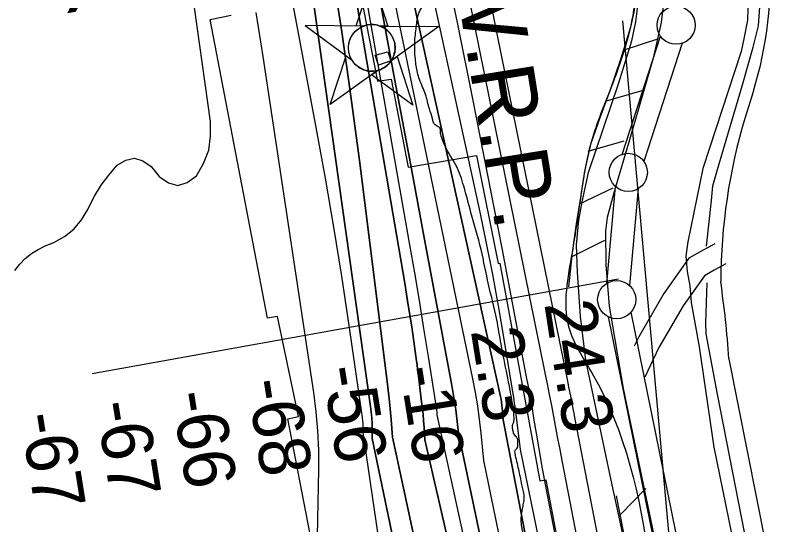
# Model space of a CAD drawing. Extents: x 3392644 to 3430565, y 576657 to 602123.
# Drawn here: x 3414227 to 3415220, y 582620 to 583288 of the extents above; entities that cross this region are included whole.
import ezdxf

# ---------------------------------------------------------------- set-up
doc = ezdxf.new("R2010")
doc.units = 0
for name, color, linetype in [('V-CHAN-DOCK', 7, 'Continuous'), ('V-CHAN-NAID', 7, 'Continuous'), ('V-FLOD-BASE', 7, 'Continuous'), ('V-LEVE-TOET', 7, 'Continuous'), ('V-RIVR-EDGE', 7, 'Continuous'), ('V-RIVR-RANG', 7, 'Continuous'), ('V-ROAD-CNTR', 7, 'Continuous'), ('V-RRAP-FSHR', 7, 'Continuous'), ('V-RRAP-RVMT', 7, 'Continuous'), ('V-SURV-LINE', 7, 'Continuous'), ('V-TOPO-DPTH', 7, 'Continuous'), ('V-TOPO-MAJR', 7, 'Continuous'), ('V-TOPO-MINR', 7, 'Continuous'), ('V-TOPO-SHOR', 7, 'Continuous'), ('V-TOPO-WATR', 7, 'Continuous'), ('V-TOPO-WATR-IDEN', 7, 'Continuous')]:
    doc.layers.add(name, color=color, linetype=linetype)

msp = doc.modelspace()

# ---------------------------------------------------------------- linework, layer by layer
at = {"layer": 'V-CHAN-DOCK'}
msp.add_lwpolyline([(3414698.49, 583235.12), (3414714.97, 583239.56), (3414719.19, 583227.57), (3414703, 583222.05), (3414698.49, 583235.12)], dxfattribs=at)
at = {"layer": 'V-CHAN-NAID'}
for points in [[(3414683.27, 583273.27), (3414673.69, 583273.34), (3414694.81, 583336.82), (3414715.04, 583273.04), (3414705.45, 583273.11), (3414703.87, 583273.69), (3414701.78, 583274.31), (3414699.74, 583274.76), (3414697.7, 583275.07), (3414696.54, 583275.18), (3414695, 583275.26), (3414693.28, 583275.26), (3414691.91, 583275.19), (3414690, 583274.99), (3414688.64, 583274.77), (3414686.85, 583274.39), (3414685.32, 583273.97), (3414684.29, 583273.64)], [(3414683.27, 583273.27), (3414606.78, 583273.81), (3414668.35, 583228.41), (3414667.24, 583230.32), (3414666.43, 583231.95), (3414665.6, 583233.92), (3414664.91, 583235.97), (3414664.54, 583237.29), (3414664.18, 583238.92), (3414663.94, 583240.37), (3414663.75, 583241.96), (3414663.64, 583243.7), (3414663.63, 583245.28), (3414663.73, 583247.35), (3414663.92, 583248.97), (3414664.31, 583251.18), (3414664.79, 583253.1), (3414665.39, 583254.99), (3414666.05, 583256.66), (3414666.77, 583258.25), (3414667.59, 583259.79), (3414668.65, 583261.52), (3414669.68, 583262.99), (3414670.68, 583264.26), (3414671.68, 583265.41), (3414672.99, 583266.75), (3414674.04, 583267.71), (3414675.76, 583269.11), (3414676.97, 583269.98), (3414678.66, 583271.05), (3414680.39, 583271.99), (3414681.83, 583272.68)], [(3414705.45, 583273.11), (3414781.94, 583272.57), (3414719.74, 583228.05), (3414720.65, 583229.54), (3414721.63, 583231.38), (3414722.34, 583232.97), (3414723.08, 583234.92), (3414723.63, 583236.71), (3414724.03, 583238.35), (3414724.39, 583240.36), (3414724.57, 583241.93), (3414724.7, 583244.14), (3414724.67, 583246.2), (3414724.48, 583248.42), (3414724.21, 583250.18), (3414723.72, 583252.41), (3414723.08, 583254.55), (3414722.33, 583256.53), (3414721.68, 583257.97), (3414720.68, 583259.89), (3414719.62, 583261.61), (3414718.4, 583263.31), (3414717.14, 583264.85), (3414715.87, 583266.22), (3414714.24, 583267.75), (3414712.49, 583269.16), (3414710.81, 583270.34), (3414708.92, 583271.47), (3414707.45, 583272.23)], [(3414701.71, 583215.14), (3414639.51, 583170.62), (3414660.63, 583234.1), (3414668.35, 583228.41), (3414668.98, 583227.45), (3414670.37, 583225.59), (3414671.58, 583224.17), (3414673.05, 583222.67), (3414674.44, 583221.42), (3414675.89, 583220.26), (3414677.29, 583219.28), (3414678.97, 583218.24), (3414680.68, 583217.33), (3414682.48, 583216.52), (3414683.92, 583215.96), (3414685.55, 583215.43), (3414687.77, 583214.87), (3414689.31, 583214.58), (3414691.33, 583214.33), (3414692.87, 583214.22), (3414694.73, 583214.2), (3414696.42, 583214.28), (3414698.13, 583214.45), (3414700.03, 583214.76)], [(3414719.74, 583228.05), (3414727.54, 583233.63), (3414747.76, 583169.85), (3414693.91, 583209.56), (3414701.71, 583215.14), (3414703.38, 583215.62), (3414704.99, 583216.18), (3414707.15, 583217.09), (3414708.88, 583217.98), (3414710.75, 583219.09), (3414712.48, 583220.3), (3414714.04, 583221.55), (3414715.32, 583222.71), (3414716.71, 583224.13), (3414717.91, 583225.54), (3414719.03, 583227.01)]]:
    msp.add_lwpolyline(points, close=True, dxfattribs=at)
msp.add_circle((3414694.16, 583244.74), 30.54, dxfattribs=at)
at = {"layer": 'V-FLOD-BASE'}
msp.add_lwpolyline([(3415036.15, 583594.1), (3415059.92, 583478.61), (3415075.05, 583377.75), (3415077.8, 583343.95), (3415077.17, 583313.67), (3415072.99, 583277.94), (3415062.38, 583231.33), (3415031.25, 583124.55), (3415011.97, 583058.15), (3415002.28, 583022.54), (3414999.86, 583005.37), (3415000.31, 582960.6), (3415004.71, 582906.8), (3415023.14, 582798.99), (3415063.23, 582606.71), (3415128.06, 582278.27), (3415163.25, 582111.18)], dxfattribs=at)
at = {"layer": 'V-LEVE-TOET'}
for points in [[(3415186.6, 583312.7), (3415185.94, 583281.04), (3415181.3, 583256.35), (3415177.52, 583239.9), (3415127.52, 583086.67), (3415107.63, 582990.68), (3415105.18, 582972.13), (3415106.83, 582952.13), (3415110.57, 582933.46), (3415112.19, 582911.39), (3415122.69, 582853.32), (3415142.01, 582722.08), (3415168.89, 582589.99), (3415225.17, 582314.75), (3415263.58, 582111.54)], [(3415131.02, 582111.06), (3415130.78, 582112.21), (3415086.3, 582325.92), (3415049.01, 582487.15), (3415007.52, 582678.76), (3414974.27, 582835.77), (3414967.2, 582893.07), (3414963.57, 582950.99), (3414962.25, 582986.83), (3414964.98, 583019.14), (3414969.61, 583043.15), (3414977.98, 583081.54), (3415016.89, 583197.8), (3415034.57, 583253.91), (3415039.91, 583278.59), (3415043.24, 583306.75)]]:
    msp.add_lwpolyline(points, dxfattribs=at)
at = {"layer": 'V-RIVR-EDGE'}
msp.add_spline([(3415011.94, 582110.63), (3415011.25, 582113.67), (3415005.32, 582138.35), (3414994.86, 582182.43), (3414988.58, 582209.22), (3414983.35, 582231.44), (3414985.12, 582233.19), (3414986.19, 582238.83), (3414984.79, 582244.82), (3414980.24, 582254.7), (3414972.18, 582274.8), (3414966.59, 582294.55), (3414960.3, 582316.41), (3414955.45, 582346.73), (3414949.18, 582375.99), (3414950.95, 582383.04), (3414951.67, 582387.62), (3414950.97, 582391.14), (3414945.72, 582402.78), (3414945.03, 582408.42), (3414945.04, 582414.41), (3414949.28, 582417.22), (3414948.23, 582420.4), (3414946.12, 582423.22), (3414938.73, 582427.47), (3414936.98, 582430.64), (3414936.99, 582436.28), (3414937.02, 582447.2), (3414934.93, 582458.84), (3414931.08, 582468.71), (3414926.53, 582481.41), (3414920.24, 582500.45), (3414911.86, 582534.3), (3414906.27, 582553.7), (3414906.29, 582561.1), (3414906.31, 582567.09), (3414904.56, 582573.79), (3414896.86, 582596.71), (3414892.32, 582609.76), (3414889.88, 582622.45), (3414889.9, 582631.96), (3414892.05, 582644.64), (3414893.48, 582651.69), (3414893.49, 582658.74), (3414890.71, 582672.84), (3414886.53, 582692.93), (3414881.65, 582714.09), (3414881.66, 582717.61), (3414884.84, 582721.48), (3414885.2, 582726.06), (3414885.22, 582732.05), (3414882.41, 582736.64), (3414880.3, 582739.11), (3414878.91, 582744.4), (3414878.21, 582748.98), (3414879.99, 582755.32), (3414880.36, 582760.61), (3414876.9, 582787.39), (3414871.33, 582816.66), (3414863.33, 582856.85), (3414857.77, 582888.93), (3414846.96, 582935.11), (3414837.21, 582980.59), (3414823.94, 583029.25), (3414814.51, 583063.81), (3414804.71, 583090.26), (3414795.23, 583106.5), (3414789.62, 583117.08), (3414785.77, 583126.96), (3414784.03, 583135.42), (3414784.04, 583138.94), (3414782.28, 583140.71), (3414777, 583143.89), (3414774.54, 583148.13), (3414773.5, 583152.36), (3414769.65, 583164.7), (3414764.41, 583183.74), (3414756.71, 583203.14), (3414753.91, 583212.31), (3414751.14, 583230.29), (3414750.49, 583254.25), (3414752.66, 583274.68), (3414756.22, 583291.24), (3414759.05, 583296.52), (3414762.6, 583304.61), (3414762.97, 583313.77), (3414763, 583322.93), (3414759.15, 583333.51), (3414751.07, 583343.75), (3414748.26, 583350.1), (3414748.27, 583353.27), (3414745.82, 583358.57), (3414741.95, 583363.86), (3414741.61, 583366.33), (3414743.04, 583373.73), (3414742.35, 583381.83), (3414734.29, 583399.47), (3414725.87, 583414.29), (3414718.49, 583423.12), (3414711.1, 583426.66), (3414699.48, 583428.1), (3414691.38, 583433.4), (3414685.06, 583440.12), (3414679.79, 583448.94), (3414677.37, 583465.15), (3414677.39, 583475.02), (3414685.18, 583487.33), (3414688.37, 583497.9), (3414689.82, 583515.16), (3414691.27, 583528.19), (3414691.65, 583541.94), (3414694.16, 583557.08), (3414696.67, 583573.99), (3414700.9, 583576.8), (3414705.48, 583576.79), (3414712.53, 583576.77), (3414714.65, 583578.17), (3414715.71, 583581.69), (3414716.08, 583589.09), (3414715.07, 583606.71), (3414713.7, 583624.69), (3414709.53, 583645.14), (3414702.19, 583671.58), (3414689.95, 583708.26), (3414675.26, 583753.4), (3414668.97, 583773.15), (3414667.95, 583789.71), (3414665.86, 583797.47), (3414663.78, 583814.39), (3414662.06, 583831.31), (3414657.55, 583856.69), (3414652.01, 583896.52), (3414646.08, 583921.2), (3414638.07, 583960.69), (3414633.91, 583989.95), (3414631.51, 584016.73), (3414630.52, 584040.7), (3414627.38, 584055.51), (3414624.59, 584068.2), (3414615.13, 584089.36), (3414609.17, 584100.65), (3414604.63, 584118.64), (3414602.91, 584134.15), (3414602.94, 584148.24), (3414607.92, 584164.09), (3414607.59, 584174.66), (3414606.56, 584186.29), (3414603.08, 584202.15), (3414597.84, 584221.9), (3414587.01, 584259.28), (3414577.21, 584284.67), (3414563.19, 584316.07), (3414556.89, 584333.7), (3414552.7, 584347.81), (3414552.72, 584358.38), (3414554.86, 584366.48), (3414565.48, 584386.54), (3414574.33, 584406.25), (3414577.89, 584417.16), (3414577.2, 584425.27), (3414574.75, 584433.03), (3414570.55, 584441.85), (3414564.57, 584448.21), (3414550.49, 584454.23), (3414538.53, 584460.25), (3414527.27, 584467.33), (3414521.29, 584472.28), (3414516.02, 584479.69)], degree=3, dxfattribs=at)
at = {"layer": 'V-RIVR-RANG'}
msp.add_line((3415017.16, 582942.05), (3414328.24, 582817.95), dxfattribs=at)
at = {"layer": 'V-ROAD-CNTR'}
for points in [[(3415193.63, 583188.38), (3415182.82, 583153.67)], [(3415143.34, 582988.29), (3415127.79, 582979.8), (3415109.26, 582969.28), (3415076.52, 582923.4), (3415043.51, 582866.67), (3415037.66, 582854.44)], [(3415157.72, 582961.97), (3415142.39, 582953.59), (3415129.83, 582946.46), (3415101.75, 582907.11), (3415070.05, 582852.64), (3415051.38, 582813.55)], [(3415161.6, 582837.88), (3415305.19, 582114.83)]]:
    msp.add_lwpolyline(points, dxfattribs=at)
for centre, radius, start, end in [((3414715.18, 583336.43), 500.83, 342.80694, 3.91232), ((3415912.22, 582935.16), 761.43, 163.32294, 179.71114), ((3413810.02, 582744.59), 1354.8, 3.94851, 8.25016)]:
    msp.add_arc(centre, radius, start, end, dxfattribs=at)
at = {"layer": 'V-RRAP-FSHR'}
for p, q in [((3415023.35, 583241.78), (3415069.82, 583256.78)), ((3415001.29, 583175.35), (3415048.14, 583189.1)), ((3414977.41, 583109.56), (3415024.33, 583123.08)), ((3414965.92, 583040.42), (3415009.9, 583061.63)), ((3414955.47, 582971.21), (3414999.14, 582993.07)), ((3415018.85, 582632.86), (3415052.7, 582668.06))]:
    msp.add_line(p, q, dxfattribs=at)
for points in [[(3415003.54, 583533.19), (3415007.38, 583520.3), (3415020.28, 583473.21), (3415031.99, 583425.41), (3415038.57, 583387.28), (3415041.24, 583349.1), (3415039.96, 583310.51), (3415037.18, 583291.23), (3415032.65, 583271.99), (3415019.61, 583229.65), (3415005.65, 583188.27), (3414992.43, 583153.35), (3414980.31, 583118.03), (3414973.2, 583085.1), (3414967.78, 583051.84), (3414961.85, 583014.41), (3414956.32, 582976.94), (3414951.47, 582932.04)], [(3415013.81, 582658.47), (3415032.62, 582562.77), (3415083.41, 582306.35), (3415123.42, 582111.03)]]:
    msp.add_lwpolyline(points, dxfattribs=at)
msp.add_spline([(3414988.21, 583582.96), (3415007.38, 583520.3), (3415031.99, 583425.41), (3415041.24, 583349.1), (3415032.65, 583271.99), (3415005.65, 583188.27), (3414980.31, 583118.03), (3414967.78, 583051.84), (3414956.32, 582976.94), (3414951.65, 582879.9), (3414982.23, 582819.21), (3415083.41, 582306.35), (3415123.24, 582111.03)], degree=3, dxfattribs=at)
at = {"layer": 'V-RRAP-RVMT'}
for p, q in [((3414662.43, 583403.08), (3414701.64, 583200.99)), ((3414482.37, 583281.92), (3414509.93, 583287.51)), ((3414557.7, 582890.74), (3414482.37, 583281.92)), ((3414701.64, 583200.99), (3414719.54, 583203.91)), ((3414719.54, 583203.91), (3414741.67, 583088.44)), ((3414741.67, 583088.44), (3414831.08, 583103.97)), ((3414831.08, 583103.97), (3414859.57, 582962.59)), ((3414859.57, 582962.59), (3414861.92, 582962.91)), ((3414861.92, 582962.91), (3414914.23, 582678.2)), ((3414570.67, 582893.01), (3414557.7, 582890.74)), ((3414598.01, 582762.25), (3414570.67, 582893.01)), ((3414584.21, 582759.11), (3414598.01, 582762.25)), ((3414637.55, 582483.52), (3414584.21, 582759.11)), ((3414914.23, 582678.2), (3414921.73, 582679.37)), ((3414921.73, 582679.37), (3414949.69, 582533.57))]:
    msp.add_line(p, q, dxfattribs=at)
at = {"layer": 'V-SURV-LINE'}
for points in [[(3415021.77, 583105.33), (3415072.05, 583260.01)], [(3415100.59, 583250.75), (3415050.31, 583096.07)], [(3415001.59, 582936.41), (3415013.12, 583063.16)], [(3415042.99, 583060.44), (3415031.47, 582933.7)], [(3415033.4, 582898.58), (3415193.35, 582111.29)], [(3415162.76, 582111.17), (3415004.01, 582892.59)]]:
    msp.add_lwpolyline(points, dxfattribs=at)
for centre in [(3415092.5, 583274.39), (3415029.86, 583081.69), (3415014.72, 582915.16)]:
    msp.add_circle(centre, 25, dxfattribs=at)
at = {"layer": 'V-TOPO-DPTH'}
for points in [[(3414406.42, 584941.91), (3414522.36, 584270.42), (3414522.43, 584270.03), (3414522.49, 584269.65), (3414522.89, 584267.36), (3414523.1, 584266.25), (3414523.28, 584265.32), (3414635.45, 583677.6), (3414642.03, 583643), (3414648.57, 583608.4), (3414655.07, 583573.79), (3414661.54, 583539.17), (3414686.49, 583405.14), (3414705.42, 583303.5), (3414724.35, 583201.87), (3414743.31, 583100.24), (3414762.28, 582998.61), (3414798.86, 582802.66), (3414801.56, 582787.11), (3414803.98, 582771.52), (3414806, 582755.88), (3414807.76, 582740.19), (3414939.76, 582110.36)], [(3414406.42, 584941.91), (3414522.36, 584270.42), (3414522.43, 584270.03), (3414522.49, 584269.65), (3414522.89, 584267.36), (3414523.1, 584266.25), (3414523.28, 584265.32), (3414635.45, 583677.6), (3414642.03, 583643), (3414648.57, 583608.4), (3414655.07, 583573.79), (3414661.54, 583539.17), (3414686.49, 583405.14), (3414705.42, 583303.5), (3414724.35, 583201.87), (3414743.31, 583100.24), (3414762.28, 582998.61), (3414798.86, 582802.66), (3414801.56, 582787.11), (3414803.98, 582771.52), (3414806, 582755.88), (3414807.76, 582740.19), (3414939.76, 582110.36)], [(3414906.69, 582110.24), (3414763.53, 582731.67), (3414763.06, 582739.96), (3414762.54, 582748.25), (3414761.91, 582756.53), (3414761.18, 582764.81), (3414760.31, 582773.07), (3414759.35, 582781.32), (3414754.22, 582822.25), (3414750.43, 582850.93), (3414746.39, 582879.57), (3414741.95, 582908.15), (3414737.26, 582936.7), (3414630.27, 583560.78)], [(3414630.27, 583560.78), (3414737.26, 582936.7), (3414741.95, 582908.15), (3414746.39, 582879.57), (3414750.43, 582850.93), (3414754.22, 582822.25), (3414759.35, 582781.32), (3414760.31, 582773.07), (3414761.18, 582764.81), (3414761.91, 582756.53), (3414762.54, 582748.25), (3414763.06, 582739.96), (3414763.53, 582731.67), (3414906.69, 582110.24)], [(3414824.64, 582109.94), (3414694.58, 582733.54), (3414694.69, 582743.99), (3414694.43, 582754.42), (3414693.61, 582764.82), (3414692.43, 582775.2), (3414596.3, 583456.6)], [(3414824.64, 582109.94), (3414694.58, 582733.54), (3414694.69, 582743.99), (3414694.43, 582754.42), (3414693.61, 582764.82), (3414692.43, 582775.2), (3414596.3, 583456.6)], [(3415030.39, 582110.69), (3414926.34, 582648.14), (3414921.96, 582671.21), (3414917.71, 582694.3), (3414913.62, 582717.42), (3414909.66, 582740.57), (3414906.86, 582757.28), (3414904.33, 582772.08), (3414901.74, 582786.86), (3414899.05, 582801.62), (3414896.29, 582816.37), (3414864.68, 582982.61), (3414845.77, 583080.42), (3414826.46, 583178.14), (3414806.55, 583275.74), (3414786.23, 583373.26)], [(3414856.12, 582110.06), (3414721.22, 582735.12), (3414719.67, 582758.36), (3414717.49, 582781.55), (3414714.89, 582804.7), (3414677.97, 583097.2), (3414666.76, 583181.41), (3414654.81, 583265.51), (3414641.72, 583349.44)], [(3414641.72, 583349.44), (3414654.81, 583265.51), (3414666.76, 583181.41), (3414677.97, 583097.2), (3414714.89, 582804.7), (3414717.49, 582781.55), (3414719.67, 582758.36), (3414721.22, 582735.12), (3414856.12, 582110.06)], [(3414990.74, 582110.55), (3414866.11, 582758.07), (3414865.85, 582761.89), (3414865.57, 582765.71), (3414865.25, 582769.53), (3414864.9, 582773.34), (3414864.47, 582777.14), (3414863.95, 582780.93), (3414863.29, 582784.69), (3414862.53, 582788.44), (3414749.03, 583303.04)], [(3414749.03, 583303.04), (3414862.53, 582788.44), (3414863.29, 582784.69), (3414863.95, 582780.93), (3414864.47, 582777.14), (3414864.9, 582773.34), (3414865.25, 582769.53), (3414865.57, 582765.71), (3414865.85, 582761.89), (3414866.11, 582758.07), (3414990.74, 582110.55)]]:
    msp.add_lwpolyline(points, dxfattribs=at)
at = {"layer": 'V-TOPO-MAJR'}
for points in [[(3414544.79, 583546.37), (3414621.4, 583138.12), (3414633.01, 583074.08), (3414644.09, 583009.95), (3414654.38, 582945.69), (3414664.13, 582881.34), (3414681.66, 582760.7), (3414682.1, 582756.6), (3414682.35, 582752.49), (3414682.31, 582748.38), (3414682.07, 582744.26), (3414774.91, 582109.76)], [(3415131.76, 582111.06), (3415124.68, 582169.34), (3415110.6, 582305.15), (3415022.72, 583280)]]:
    msp.add_lwpolyline(points, dxfattribs=at)
at = {"layer": 'V-TOPO-MINR'}
for points in [[(3414939.76, 582110.36), (3414807.76, 582740.19), (3414806, 582755.88), (3414803.98, 582771.52), (3414801.56, 582787.11), (3414798.86, 582802.66), (3414762.28, 582998.61), (3414743.31, 583100.24), (3414724.35, 583201.87), (3414705.42, 583303.5), (3414686.49, 583405.14), (3414661.54, 583539.17), (3414655.07, 583573.79), (3414648.57, 583608.4), (3414642.03, 583643), (3414635.45, 583677.6), (3414523.28, 584265.32), (3414523.1, 584266.25), (3414522.89, 584267.36), (3414522.49, 584269.65), (3414522.43, 584270.03), (3414522.36, 584270.42), (3414406.42, 584941.91)], [(3414906.69, 582110.24), (3414763.53, 582731.67), (3414763.06, 582739.96), (3414762.54, 582748.25), (3414761.91, 582756.53), (3414761.18, 582764.81), (3414760.31, 582773.07), (3414759.35, 582781.32), (3414754.22, 582822.25), (3414750.43, 582850.93), (3414746.39, 582879.57), (3414741.95, 582908.15), (3414737.26, 582936.7), (3414630.27, 583560.78)], [(3414922.42, 582110.3), (3414779.81, 582764.58), (3414779.49, 582767.67), (3414779.09, 582770.75), (3414778.65, 582773.83), (3414768.22, 582840.8), (3414762.42, 582877.34), (3414756.48, 582913.85), (3414750.33, 582950.33), (3414744.03, 582986.79), (3414644.92, 583550.45)], [(3415013.37, 582110.63), (3414888.73, 582719.12), (3414881.6, 582775.2), (3414881.05, 582779.37), (3414880.47, 582783.52), (3414879.84, 582787.67), (3414879.18, 582791.81), (3414867.01, 582865.86), (3414859.94, 582906.96), (3414852.44, 582947.99), (3414844.32, 582988.89), (3414835.78, 583029.72), (3414722.68, 583550.52)], [(3414226.96, 582953.31), (3414233.22, 582961.54), (3414240.6, 582968.83), (3414248.51, 582975.36), (3414257.23, 582980.78), (3414266.49, 582985.44), (3414277.73, 582990.17), (3414291.68, 582998.02), (3414304.03, 583007.53), (3414313.96, 583019.53), (3414322.29, 583033.2), (3414323.31, 583035.4), (3414331.15, 583050.4), (3414339.88, 583064.81), (3414349.95, 583078.31), (3414360.9, 583091.22), (3414372.3, 583097.91), (3414383.55, 583100.52), (3414394.55, 583097.03), (3414405.38, 583089.45), (3414415.78, 583076.38), (3414428.06, 583068.19), (3414440.28, 583064.77), (3414452.41, 583068.52), (3414464.46, 583077.04), (3414474.01, 583093.55), (3414480.74, 583110.8), (3414483.22, 583129.14), (3414482.88, 583148.21), (3414430.33, 583524.78)], [(3414596.3, 583456.6), (3414692.43, 582775.2), (3414693.61, 582764.82), (3414694.43, 582754.42), (3414694.69, 582743.99), (3414694.58, 582733.54), (3414824.64, 582109.94)], [(3415030.39, 582110.69), (3414926.34, 582648.14), (3414921.96, 582671.21), (3414917.71, 582694.3), (3414913.62, 582717.42), (3414909.66, 582740.57), (3414906.86, 582757.28), (3414904.33, 582772.08), (3414901.74, 582786.86), (3414899.05, 582801.62), (3414896.29, 582816.37), (3414864.68, 582982.61), (3414845.77, 583080.42), (3414826.46, 583178.14), (3414806.55, 583275.74), (3414786.23, 583373.26)], [(3414856.12, 582110.06), (3414721.22, 582735.12), (3414719.67, 582758.36), (3414717.49, 582781.55), (3414714.89, 582804.7), (3414677.97, 583097.2), (3414666.76, 583181.41), (3414654.81, 583265.51), (3414641.72, 583349.44)], [(3414962.99, 582110.45), (3414840.82, 582704.43), (3414839.16, 582722.38), (3414837.41, 582740.32), (3414835.32, 582758.21), (3414832.86, 582776.05), (3414829.86, 582793.8), (3414826.48, 582811.5), (3414716.85, 583342.22)], [(3415085.84, 582110.89), (3414960.06, 582760.98), (3414958.96, 582766.65), (3414957.86, 582772.31), (3414956.75, 582777.98), (3414955.64, 582783.64), (3414954.52, 582789.31), (3414953.4, 582794.97), (3414952.26, 582800.63), (3414951.12, 582806.29), (3414858.42, 583263.27), (3414846.05, 583324.77)], [(3415058.23, 582110.79), (3414943.27, 582704.78), (3414940.51, 582719.11), (3414937.78, 582733.45), (3414935.07, 582747.79), (3414932.4, 582762.14), (3414929.7, 582776.48), (3414926.95, 582790.81), (3414924.14, 582805.13), (3414921.28, 582819.45), (3414822.23, 583308.63)], [(3414589.87, 582109.09), (3414590.65, 582117.86), (3414591.55, 582126.96), (3414603.95, 582245.07), (3414610.24, 582313.27), (3414615.39, 582381.55), (3414618.82, 582449.94), (3414621.11, 582518.4), (3414624.75, 582693.02), (3414624.63, 582718.24), (3414623.65, 582743.41), (3414621.39, 582768.49), (3414618.28, 582793.52), (3414552.01, 583233.37), (3414542.93, 583291.18)]]:
    msp.add_lwpolyline(points, dxfattribs=at)
at = {"layer": 'V-TOPO-SHOR'}
for points in [[(3415132.11, 582984.97), (3415138.81, 583044.88), (3415140.56, 583063.95), (3415146.47, 583085.67), (3415179.47, 583196.23), (3415193.46, 583245.75), (3415200.18, 583273.6), (3415203, 583311.07), (3415199.11, 583354.15), (3415194.1, 583408.84), (3415175.96, 583521.14), (3415149.25, 583648.63), (3415118.97, 583768.68), (3415062.77, 583987.54), (3415036.89, 584089.08), (3415033.23, 584110.31)], [(3415285.21, 582111.62), (3415235.58, 582346.11), (3415182.33, 582608.59), (3415146.53, 582791.54), (3415131.78, 582870.32), (3415131.39, 582884.66), (3415133.16, 582937.18)]]:
    msp.add_lwpolyline(points, dxfattribs=at)
at = {"layer": 'V-TOPO-WATR'}
msp.add_lwpolyline([(3414990.74, 582110.55), (3414866.11, 582758.07), (3414865.85, 582761.89), (3414865.57, 582765.71), (3414865.25, 582769.53), (3414864.9, 582773.34), (3414864.47, 582777.14), (3414863.95, 582780.93), (3414863.29, 582784.69), (3414862.53, 582788.44), (3414749.03, 583303.04)], dxfattribs=at)

# ---------------------------------------------------------------- texts
at = {"layer": 'V-CHAN-NAID'}
msp.add_text('LAFARGE CEMENT (167.9) (2)', height=100, rotation=10.14368, dxfattribs=at).set_placement((3412672.7, 583030.23))
at = {"layer": 'V-RIVR-RANG'}
for s, rotation, p in [('24.3', 278.77833, (3414919.82, 582909.94)), ('2.3', 279.06297, (3414823.59, 582874.64)), ('-56', 279.06297, (3414628.91, 582825.39)), ('-16', 279.06297, (3414730.2, 582825.27)), ('-68', 279.06297, (3414530.37, 582808.32)), ('-66', 279.06297, (3414431.67, 582792.29)), ('-67', 279.06297, (3414332.46, 582779.39)), ('-67', 279.06297, (3414233.67, 582763.88))]:
    msp.add_text(s, height=67, rotation=rotation, dxfattribs=at).set_placement(p)
at = {"layer": 'V-TOPO-WATR-IDEN'}
msp.add_text('L.W.R.P.', height=83, rotation=279.19153, dxfattribs=at).set_placement((3414785.79, 583441.78))

doc.saveas('drawing.dxf')
